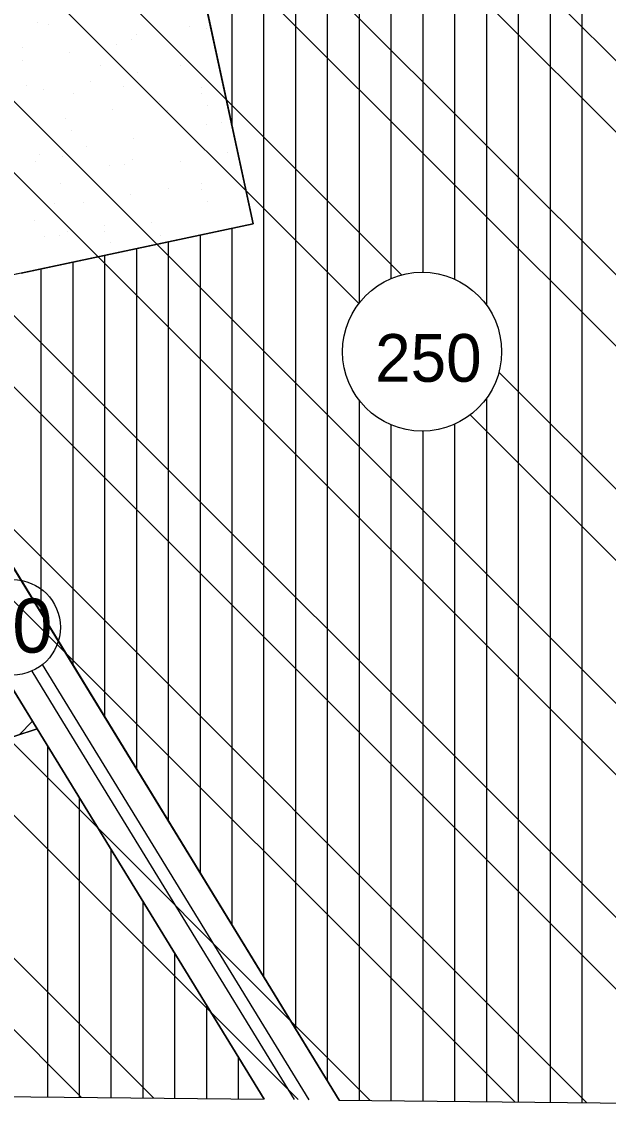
# Model space of a CAD drawing. Extents: x 409341 to 428634, y 4447481 to 4463281.
# Drawn here: x 420722.5 to 420906.8, y 4457776.1 to 4458119.5 of the extents above; entities that cross this region are included whole.
import ezdxf

# ---------------------------------------------------------------- set-up
doc = ezdxf.new("R2010")
doc.units = 0
for name, color, linetype in [('ADA', 7, 'Continuous'), ('ADAKENARI', 7, 'Continuous'), ('Default', 7, 'Continuous'), ('KALDIRIM', 7, 'Continuous'), ('KD_DAIRE', 7, 'Continuous'), ('KD_YGEN', 7, 'Continuous'), ('PL_AYA_PARK_DINLENME', 7, 'Continuous'), ('PL_K_K_D_K_C_A', 7, 'Continuous'), ('PL_KON_MEV_250', 7, 'Continuous'), ('SM_DAIRE', 7, 'Continuous'), ('SM_TAKS', 7, 'Continuous'), ('SN_TR_SIVILASMA', 7, 'Continuous'), ('TR_KONUTDISIKCA', 7, 'Continuous'), ('TR_ORTAYOGUNKONUT', 7, 'Continuous'), ('TR_PARKALANI', 7, 'Continuous')]:
    doc.layers.add(name, color=color, linetype=linetype)

# ---------------------------------------------------------------- blocks, each defined once
blk = doc.blocks.new('POINT_DISPLAY')
at = {"layer": 'Default'}
blk.add_line((0, 0), (0, 0), dxfattribs=at)

msp = doc.modelspace()

# ---------------------------------------------------------------- linework, layer by layer
at = {"layer": 'ADA'}
for q in [(420775.05, 4458149.45), (420669.86, 4458029.4)]:
    msp.add_line((420795.15, 4458056.03), q, dxfattribs=at)
at = {"layer": 'ADAKENARI'}
for p, q in [((420491.4, 4458282.6), (420727.31, 4457897.27)), ((420576.48, 4458143.63), (420727.31, 4457897.27)), ((420822.23, 4457780.52), (420669.71, 4458029.64)), ((420580.61, 4457849.04), (420727.31, 4457897.27)), ((420727.31, 4457897.27), (420798.63, 4457780.77))]:
    msp.add_line(p, q, dxfattribs=at)
at = {"layer": 'KALDIRIM'}
for p, q in [((420725.59, 4457915.4), (420734.13, 4457901.45)), ((420812.79, 4457780.62), (420729.01, 4457917.47)), ((420734.13, 4457901.45), (420808.07, 4457780.67))]:
    msp.add_line(p, q, dxfattribs=at)
at = {"layer": 'KD_DAIRE'}
msp.add_circle((420719.61, 4457929.16), 15, dxfattribs=at)
at = {"layer": 'PL_AYA_PARK_DINLENME'}
for p, q in [((420795.15, 4458056.03), (420775.05, 4458149.45)), ((420722.25, 4458040.54), (420795.15, 4458056.03))]:
    msp.add_line(p, q, dxfattribs=at)
at = {"layer": 'PL_K_K_D_K_C_A'}
msp.add_lwpolyline([(420720.61, 4457895.07), (420727.31, 4457897.27), (420576.48, 4458143.63), (420548.37, 4458189.54), (420546.29, 4458189.17), (420541.5, 4458188.3), (420531.5, 4458186.48), (420521.5, 4458184.66), (420511.5, 4458182.85), (420501.5, 4458181.03), (420491.5, 4458179.21), (420491.25, 4458179.17), (420481.5, 4458177.4), (420471.5, 4458175.58), (420461.5, 4458173.76), (420451.5, 4458171.95), (420441.5, 4458170.13), (420436.2, 4458169.17), (420445.81, 4458143.63), (420500.41, 4457998.46)], dxfattribs=at)
at = {"layer": 'PL_KON_MEV_250'}
for p, q in [((420669.86, 4458029.4), (420822.23, 4457780.52)), ((420692.29, 4457781.9), (420798.63, 4457780.77)), ((420822.23, 4457780.52), (420940.52, 4457779.27))]:
    msp.add_line(p, q, dxfattribs=at)
for points in [[(420823.57, 4458329.25), (420740.42, 4458310.37), (420744.27, 4458292.48), (420775.05, 4458149.45), (420795.15, 4458056.03), (420722.25, 4458040.54), (420669.86, 4458029.4)], [(420798.63, 4457780.77), (420727.31, 4457897.27), (420580.61, 4457849.04), (420614.35, 4457787.49), (420675.71, 4457809.73), (420692.29, 4457781.9)]]:
    msp.add_lwpolyline(points, dxfattribs=at)
at = {"layer": 'SM_DAIRE'}
msp.add_circle((420848.27, 4458015.81), 25, dxfattribs=at)
at = {"layer": 'SN_TR_SIVILASMA'}
for p, q in [((421240.43, 4457776.1), (420847.49, 4458169.04)), ((421217.74, 4457776.34), (420847.49, 4458146.59)), ((420809.31, 4457780.66), (420446.34, 4458143.63)), ((420832, 4457780.42), (420468.79, 4458143.63)), ((420877.38, 4457779.94), (420513.69, 4458143.63)), ((420900.07, 4457779.7), (420536.14, 4458143.63)), ((420945.45, 4457779.22), (420581.04, 4458143.63)), ((420968.14, 4457778.98), (420603.49, 4458143.63)), ((421013.52, 4457778.5), (420648.4, 4458143.63)), ((421036.21, 4457778.26), (420670.85, 4458143.63)), ((420828.4, 4458030.98), (420715.75, 4458143.63)), ((420841.86, 4458039.97), (420738.2, 4458143.63)), ((421149.66, 4457777.06), (420783.1, 4458143.63)), ((421172.36, 4457776.82), (420805.55, 4458143.63)), ((420763.93, 4457781.14), (420413.37, 4458131.7)), ((420741.24, 4457781.38), (420405.02, 4458117.6)), ((421104.28, 4457777.54), (420872.43, 4458009.39)), ((421081.59, 4457777.78), (420863.44, 4457995.94))]:
    msp.add_line(p, q, dxfattribs=at)
at = {"layer": 'TR_KONUTDISIKCA'}
msp.add_line((420721.62, 4457895.4), (420725.86, 4457899.64), dxfattribs=at)
at = {"layer": 'TR_ORTAYOGUNKONUT'}
for p, q in [((420888.59, 4457779.82), (420888.59, 4458333.77)), ((420898.59, 4457779.72), (420898.59, 4458334.33)), ((420828.59, 4458031.22), (420828.59, 4458330.18)), ((420838.59, 4458038.86), (420838.59, 4458331)), ((420848.59, 4458040.81), (420848.59, 4458331.55)), ((420858.59, 4458038.58), (420858.59, 4458332.11)), ((420868.59, 4458030.37), (420868.59, 4458332.66)), ((420878.59, 4457779.93), (420878.59, 4458333.22)), ((420818.59, 4457786.47), (420818.59, 4458328.12)), ((420798.59, 4457819.14), (420798.59, 4458323.58)), ((420808.59, 4457802.8), (420808.59, 4458325.85)), ((420788.59, 4458086.5), (420788.59, 4458321.3)), ((420778.59, 4457851.8), (420778.59, 4458052.51)), ((420788.59, 4457835.47), (420788.59, 4458054.64)), ((420758.59, 4457884.47), (420758.59, 4458048.26)), ((420768.59, 4457868.14), (420768.59, 4458050.39)), ((420748.59, 4457900.81), (420748.59, 4458046.14)), ((420728.59, 4457933.48), (420728.59, 4458041.88)), ((420738.59, 4457917.14), (420738.59, 4458044.01)), ((420828.59, 4457780.46), (420828.59, 4458000.39)), ((420868.59, 4457780.03), (420868.59, 4458001.24)), ((420838.59, 4457780.35), (420838.59, 4457992.76)), ((420848.59, 4457780.25), (420848.59, 4457990.81)), ((420858.59, 4457780.14), (420858.59, 4457993.04)), ((420730.61, 4457781.49), (420730.61, 4457891.87)), ((420740.61, 4457781.39), (420740.61, 4457875.54)), ((420750.61, 4457781.28), (420750.61, 4457859.2)), ((420760.61, 4457781.18), (420760.61, 4457842.87)), ((420770.61, 4457781.07), (420770.61, 4457826.54)), ((420780.61, 4457780.96), (420780.61, 4457810.2)), ((420790.61, 4457780.86), (420790.61, 4457793.87))]:
    msp.add_line(p, q, dxfattribs=at)
msp.add_lwpolyline([(420775.05, 4458149.45), (420795.15, 4458056.03), (420722.25, 4458040.54), (420669.86, 4458029.4), (420822.23, 4457780.52)], dxfattribs=at)

# ---------------------------------------------------------------- block references
at = {"layer": 'TR_PARKALANI', "xscale": 0.1, "yscale": 0.10000000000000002}
for p in [(420727.43, 4458119.26), (420730.85, 4458118.82), (420730.85, 4458118.82), (420775.06, 4458117.98), (420780.51, 4458117.52), (420780.51, 4458117.52), (420756.97, 4458114.05), (420758.63, 4458115.45), (420767.05, 4458115.05), (420767.05, 4458115.05), (420722.79, 4458111.49), (420752.28, 4458112.45), (420752.28, 4458112.45), (420722.74, 4458107.24), (420722.74, 4458107.24), (420737.51, 4458109.84), (420737.51, 4458109.84), (420747.14, 4458105.81), (420747.14, 4458105.81), (420758.94, 4458103.47), (420758.94, 4458103.47), (420772.4, 4458105.94), (420772.4, 4458105.94), (420744.17, 4458100.86), (420744.17, 4458100.86), (420723.95, 4458099.57), (420729.4, 4458098.26), (420729.4, 4458098.26), (420738.73, 4458096.96), (420754.37, 4458099.28), (420778.9, 4458098.82), (420779.06, 4458096.96), (420779.06, 4458096.96), (420765.6, 4458094.49), (420765.6, 4458094.49), (420780.87, 4458093.33), (420750.83, 4458091.88), (420750.83, 4458091.88), (420768.27, 4458091.75), (420736.06, 4458089.28), (420736.06, 4458089.28), (420780.51, 4458087.33), (420780.51, 4458087.33), (420785.21, 4458087.76), (420738.25, 4458085.3), (420757.49, 4458082.9), (420757.49, 4458082.9), (420742.72, 4458080.3), (420742.72, 4458080.3), (420727.95, 4458077.7), (420727.95, 4458077.7), (420735.25, 4458077.27), (420757.35, 4458076.12), (420757.35, 4458076.12), (420772.4, 4458075.75), (420772.4, 4458075.75), (420787.17, 4458078.35), (420787.17, 4458078.35), (420726.76, 4458075.65), (420726.76, 4458075.65), (420750.06, 4458074.31), (420750.06, 4458074.31), (420754.76, 4458074.74), (420734.61, 4458068.72), (420734.61, 4458068.72), (420768.67, 4458067.21), (420778.9, 4458068.63), (420779.06, 4458066.77), (420779.06, 4458066.77), (420732.65, 4458062.5), (420741.95, 4458062.73), (420741.95, 4458062.73), (420756.72, 4458065.33), (420756.72, 4458065.33), (420780.87, 4458063.14), (420726.49, 4458057.13), (420726.49, 4458057.13), (420748.46, 4458055.61), (420763.38, 4458056.35), (420763.38, 4458056.35), (420729.58, 4458051.88), (420729.58, 4458051.88), (420734.28, 4458052.3), (420736.87, 4458053.69), (420736.87, 4458053.69), (420748.61, 4458053.75), (420748.61, 4458053.75), (420766.06, 4458052.44), (420750.42, 4458050.12)]:
    msp.add_blockref('POINT_DISPLAY', p, dxfattribs=at)

# ---------------------------------------------------------------- texts
at = {"layer": 'KD_YGEN'}
msp.add_text('20', height=17, dxfattribs=at).set_placement((420706.84, 4457921.2))
at = {"layer": 'SM_TAKS'}
msp.add_text('250', height=15, dxfattribs=at).set_placement((420833.53, 4458006.36))

doc.saveas('drawing.dxf')
